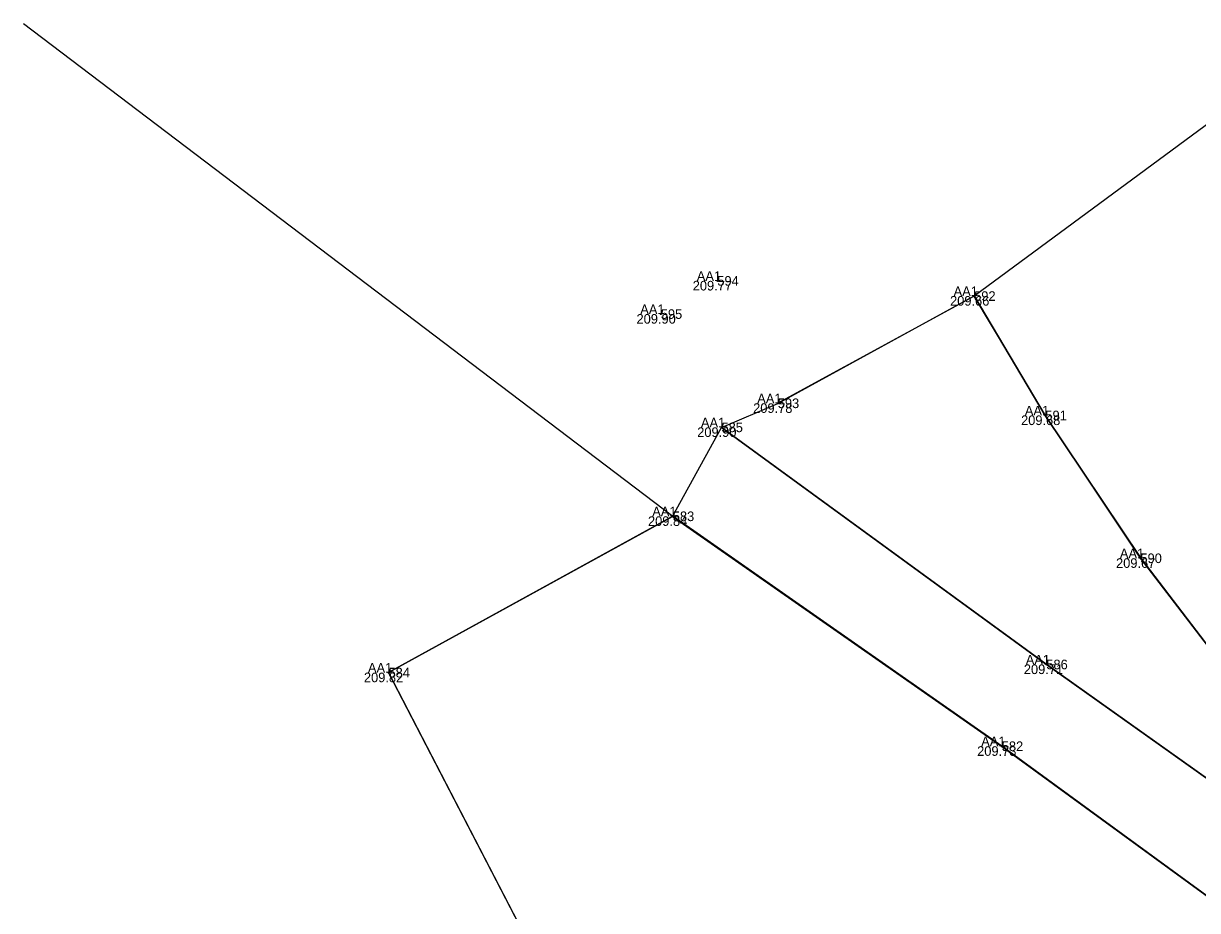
# Model space of a CAD drawing. Extents: x -263091 to -262565, y -1238731 to -1237092.
# Drawn here: x -262982.43 to -262957.98, y -1238394.45 to -1238375.98 of the extents above; entities that cross this region are included whole.
import ezdxf

# ---------------------------------------------------------------- set-up
doc = ezdxf.new("R2010")
doc.units = 0
for name, color, linetype in [('03_Asfalt', 7, 'Continuous'), ('10', 7, 'Continuous'), ('Groma (21)', 7, 'Continuous'), ('Groma (22)', 7, 'Continuous'), ('Groma (23)', 7, 'Continuous'), ('Groma (24)', 7, 'Continuous'), ('U001_Zeleň_mimo', 7, 'Continuous'), ('U002_Asfalt', 7, 'Continuous'), ('U002_Zeleň_mimo', 7, 'Continuous')]:
    doc.layers.add(name, color=color, linetype=linetype)

msp = doc.modelspace()

# ---------------------------------------------------------------- linework, layer by layer
at = {"layer": '03_Asfalt'}
for points in [[(-262967.893, -1238384.386), (-262961.125, -1238389.323), (-262954.307, -1238394.16), (-262953.782, -1238393.748), (-262956.194, -1238390.986), (-262959.165, -1238387.112), (-262961.145, -1238384.138), (-262962.629, -1238381.652), (-262966.72, -1238383.885)], [(-262954.673, -1238396.412), (-262962.054, -1238391.026), (-262968.907, -1238386.238), (-262974.83, -1238389.493)], [(-262974.83, -1238389.493), (-262966.434, -1238405.689)]]:
    msp.add_lwpolyline(points, dxfattribs=at)
at = {"layer": '10'}
msp.add_lwpolyline([(-262982.434, -1238375.977), (-262968.907, -1238386.238), (-262962.054, -1238391.026), (-262954.673, -1238396.412), (-262941.774, -1238405.784), (-262928.896, -1238415.327), (-262917.716, -1238423.993), (-262905.824, -1238433.621), (-262895.067, -1238441.663), (-262870.407, -1238460.6)], dxfattribs=at)
at = {"layer": 'Groma (21)'}
for centre in [(-262967.979, -1238381.336), (-262962.629, -1238381.652), (-262969.157, -1238382.027), (-262966.72, -1238383.885), (-262961.145, -1238384.138), (-262967.893, -1238384.386), (-262968.907, -1238386.238), (-262959.165, -1238387.112), (-262961.125, -1238389.323), (-262974.83, -1238389.493), (-262962.054, -1238391.026)]:
    msp.add_circle(centre, 0.01, dxfattribs=at)
at = {"layer": 'U001_Zeleň_mimo'}
msp.add_lwpolyline([(-262966.43, -1238405.69), (-262974.83, -1238389.49), (-262968.91, -1238386.24), (-262962.05, -1238391.03), (-262954.67, -1238396.41)], dxfattribs=at)
at = {"layer": 'U002_Asfalt'}
for points in [[(-262956.19, -1238390.99), (-262959.16, -1238387.11), (-262961.15, -1238384.14), (-262962.63, -1238381.65), (-262956.31, -1238376.99)], [(-262956.19, -1238390.99), (-262959.16, -1238387.11), (-262961.15, -1238384.14), (-262962.63, -1238381.65), (-262956.31, -1238376.99)], [(-262954.67, -1238396.41), (-262962.05, -1238391.03), (-262968.91, -1238386.24), (-262967.89, -1238384.39), (-262961.13, -1238389.32), (-262954.31, -1238394.16)], [(-262954.67, -1238396.41), (-262962.05, -1238391.03), (-262968.91, -1238386.24), (-262967.89, -1238384.39), (-262961.13, -1238389.32), (-262954.31, -1238394.16)]]:
    msp.add_lwpolyline(points, dxfattribs=at)
at = {"layer": 'U002_Zeleň_mimo'}
msp.add_lwpolyline([(-262961.15, -1238384.14), (-262959.16, -1238387.11), (-262956.19, -1238390.99), (-262953.78, -1238393.75), (-262954.31, -1238394.16), (-262961.13, -1238389.32), (-262967.89, -1238384.39), (-262966.72, -1238383.89), (-262962.63, -1238381.65)], close=True, dxfattribs=at)

# ---------------------------------------------------------------- texts
at = {"layer": 'Groma (22)'}
for s, p in [('594', (-262967.979, -1238381.436)), ('592', (-262962.629, -1238381.752)), ('595', (-262969.157, -1238382.127)), ('593', (-262966.72, -1238383.985)), ('591', (-262961.145, -1238384.238)), ('585', (-262967.893, -1238384.486)), ('583', (-262968.907, -1238386.338)), ('590', (-262959.165, -1238387.212)), ('586', (-262961.125, -1238389.423)), ('584', (-262974.83, -1238389.593)), ('582', (-262962.054, -1238391.126))]:
    msp.add_text(s, height=0.2, dxfattribs=at).set_placement(p)
at = {"layer": 'Groma (23)'}
for s, p in [('209.77', (-262968.492, -1238381.536)), ('209.66', (-262963.131, -1238381.852)), ('209.90', (-262969.663, -1238382.227)), ('209.78', (-262967.233, -1238384.085)), ('209.68', (-262961.652, -1238384.338)), ('209.90', (-262968.399, -1238384.586)), ('209.84', (-262969.424, -1238386.438)), ('209.67', (-262959.673, -1238387.312)), ('209.71', (-262961.594, -1238389.523)), ('209.82', (-262975.342, -1238389.693)), ('209.73', (-262962.567, -1238391.226))]:
    msp.add_text(s, height=0.2, dxfattribs=at).set_placement(p)
at = {"layer": 'Groma (24)'}
for p in [(-262968.407, -1238381.336), (-262963.057, -1238381.652), (-262969.585, -1238382.027), (-262967.148, -1238383.885), (-262961.573, -1238384.138), (-262968.321, -1238384.386), (-262969.335, -1238386.238), (-262959.593, -1238387.112), (-262961.553, -1238389.323), (-262975.258, -1238389.493), (-262962.482, -1238391.026)]:
    msp.add_text('AA1', height=0.2, dxfattribs=at).set_placement(p)

doc.saveas('drawing.dxf')
